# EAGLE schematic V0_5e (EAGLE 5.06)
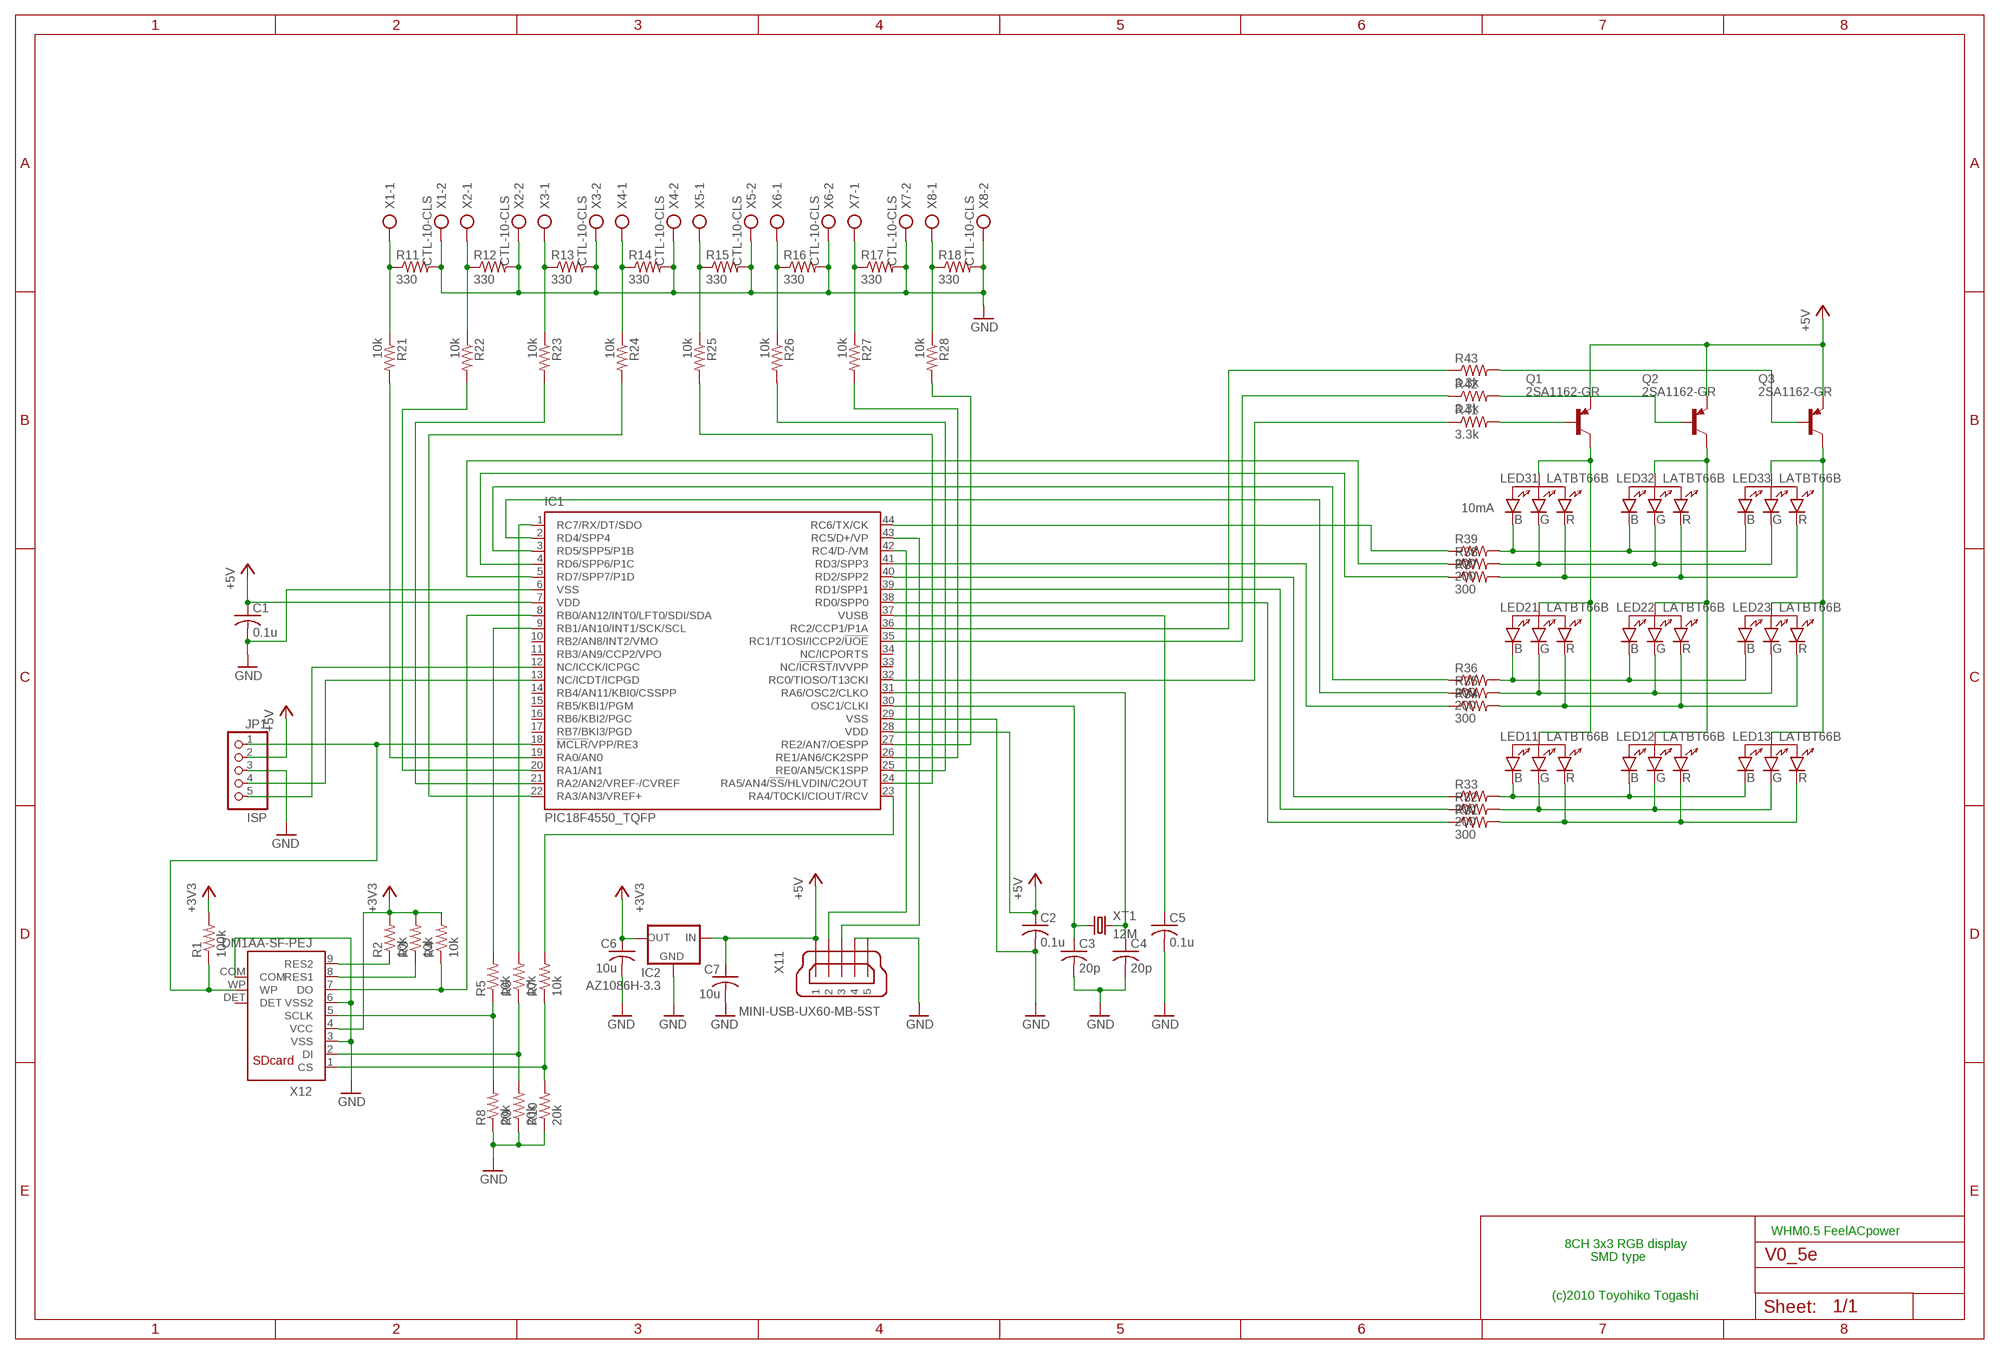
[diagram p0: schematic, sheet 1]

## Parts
C1  0.1u  C-USC0805  [C0805]
C2  0.1u  C-USC0805  [C0805]
C3  20p  C-USC0805  [C0805]
C4  20p  C-USC0805  [C0805]
C5  0.1u  C-USC0805  [C0805]
C6  10u  C-USC1206  [C1206]
C7  10u  C-USC1206  [C1206]
IC1  PIC18F4550_TQFP  [TQFP44]
IC2  AZ1086H-3.3  XC63FPP  [SOT89R]
JP1  ISP  PINHD-1X5  [1X05]
LED11  LATBT66B  [P-LCC-4]
LED12  LATBT66B  [P-LCC-4]
LED13  LATBT66B  [P-LCC-4]
LED21  LATBT66B  [P-LCC-4]
LED22  LATBT66B  [P-LCC-4]
LED23  LATBT66B  [P-LCC-4]
LED31  LATBT66B  [P-LCC-4]
LED32  LATBT66B  [P-LCC-4]
LED33  LATBT66B  [P-LCC-4]
Q1  2SA1162-GR  MMBT540LT1SMD  [SOT23-BEC]
Q2  2SA1162-GR  MMBT540LT1SMD  [SOT23-BEC]
Q3  2SA1162-GR  MMBT540LT1SMD  [SOT23-BEC]
R1  100k  R-US_M0805  [M0805]
R2  10k  R-US_M0805  [M0805]
R3  10k  R-US_M0805  [M0805]
R4  10k  R-US_M0805  [M0805]
R5  10k  R-US_M0805  [M0805]
R6  10k  R-US_M0805  [M0805]
R7  10k  R-US_M0805  [M0805]
R8  20k  R-US_M0805  [M0805]
R9  20k  R-US_M0805  [M0805]
R10  20k  R-US_M0805  [M0805]
R11  330  R-US_M0805  [M0805]
R12  330  R-US_M0805  [M0805]
R13  330  R-US_M0805  [M0805]
R14  330  R-US_M0805  [M0805]
R15  330  R-US_M0805  [M0805]
R16  330  R-US_M0805  [M0805]
R17  330  R-US_M0805  [M0805]
R18  330  R-US_M0805  [M0805]
R21  10k  R-US_M0805  [M0805]
R22  10k  R-US_M0805  [M0805]
R23  10k  R-US_M0805  [M0805]
R24  10k  R-US_M0805  [M0805]
R25  10k  R-US_M0805  [M0805]
R26  10k  R-US_M0805  [M0805]
R27  10k  R-US_M0805  [M0805]
R28  10k  R-US_M0805  [M0805]
R31  300  R-US_M0805  [M0805]
R32  200  R-US_M0805  [M0805]
R33  200  R-US_M0805  [M0805]
R34  300  R-US_M0805  [M0805]
R35  200  R-US_M0805  [M0805]
R36  200  R-US_M0805  [M0805]
R37  300  R-US_M0805  [M0805]
R38  200  R-US_M0805  [M0805]
R39  200  R-US_M0805  [M0805]
R41  3.3k  R-US_M0805  [M0805]
R42  3.3k  R-US_M0805  [M0805]
R43  3.3k  R-US_M0805  [M0805]
X1  CTL-10-CLS  AK500/2  [AK500/2]
X2  CTL-10-CLS  AK500/2  [AK500/2]
X3  CTL-10-CLS  AK500/2  [AK500/2]
X4  CTL-10-CLS  AK500/2  [AK500/2]
X5  CTL-10-CLS  AK500/2  [AK500/2]
X6  CTL-10-CLS  AK500/2  [AK500/2]
X7  CTL-10-CLS  AK500/2  [AK500/2]
X8  CTL-10-CLS  AK500/2  [AK500/2]
X11  MINI-USB-UX60-MB-5ST  [UX60-MB-5ST]
X12  DM1AA-SF-PEJ  [DM1AA]
XT1  12M  CRYSTALHC49UP  [HC49UP]

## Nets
+3V3: C6.1 IC2.3(OUT) R1.2 R2.2 R3.2 R4.2 X12.4(VCC)
+5V: C1.1 C2.1 C7.1 IC1.7(VDD) IC1.28(VDD) IC2.2(IN) JP1.2 Q1.E Q2.E Q3.E X11.1
GND: C1.2 C2.2 C3.2 C4.2 C5.2 C6.2 C7.2 IC1.6(VSS) IC1.29(VSS) IC2.1(GND) JP1.3 R8.1 R9.1 R10.1 R11.2 R12.2 R13.2 R14.2 R15.2 R16.2 R17.2 R18.2 X1.2 X2.2 X3.2 X4.2 X5.2 X6.2 X7.2 X8.2 X11.4 X12.3(VSS) X12.6(VSS2) X12.COM
N$1: IC1.39(RD1/SPP1) R32.1
N$2: IC1.22(RA3/AN3/VREF+) R24.2
N$3: IC1.21(RA2/AN2/VREF-/CVREF) R23.2
N$4: IC1.20(RA1/AN1) R22.2
N$5: R18.1 R28.1 X8.1
N$6: R5.1 R8.2 X12.5(SCLK)
N$8: R6.1 R9.2 X12.2(DI)
N$9: R7.1 R10.2 X12.1(CS)
N$10: IC1.18(!MCLR!/VPP/RE3) JP1.1 R1.1 X12.WP
N$11: LED11.P$3 LED12.P$3 LED13.P$3 R33.2
N$12: LED11.P$4 LED12.P$4 LED13.P$4 R32.2
N$13: LED11.P$1 LED12.P$1 LED13.P$1 R31.2
N$15: LED12.P$2 LED22.P$2 LED32.P$2 Q2.C
N$16: IC1.42(RC4/D-/VM) X11.2
N$17: IC1.43(RC5/D+/VP) X11.3
N$18: LED13.P$2 LED23.P$2 LED33.P$2 Q3.C
N$19: IC1.24(RA5/AN4/!SS!/HLVDIN/C2OUT) R25.2
N$20: IC1.9(RB1/AN10/INT1/SCK/SCL) R5.2
N$21: IC1.1(RC7/RX/DT/SDO) R6.2
N$22: IC1.23(RA4/T0CKI/CIOUT/RCV) R7.2
N$24: IC1.41(RD3/SPP3) R34.1
N$25: IC1.44(RC6/TX/CK) R39.1
N$26: IC1.35(RC1/T1OSI/ICCP2/!UOE) R42.1
N$28: IC1.40(RD2/SPP2) R33.1
N$29: IC1.25(RE0/AN5/CK1SPP) R26.2
N$30: IC1.13(NC/ICDT/ICPGD) JP1.4
N$31: IC1.12(NC/ICCK/ICPGC) JP1.5
N$32: IC1.26(RE1/AN6/CK2SPP) R27.2
N$33: Q1.B R41.2
N$34: IC1.27(RE2/AN7/OESPP) R28.2
N$35: Q2.B R42.2
N$36: R17.1 R27.1 X7.1
N$37: R16.1 R26.1 X6.1
N$38: R15.1 R25.1 X5.1
N$39: R14.1 R24.1 X4.1
N$40: R13.1 R23.1 X3.1
N$41: R12.1 R22.1 X2.1
N$42: R2.1 X12.9(RES2)
N$43: R3.1 X12.8(RES1)
N$44: R11.1 R21.1 X1.1
N$45: Q3.B R43.2
N$47: C4.1 IC1.31(RA6/OSC2/CLKO) XT1.2
N$49: C3.1 IC1.30(OSC1/CLKI) XT1.1
N$50: IC1.19(RA0/AN0) R21.2
N$51: LED31.P$3 LED32.P$3 LED33.P$3 R39.2
N$52: C5.1 IC1.37(VUSB)
N$53: LED31.P$4 LED32.P$4 LED33.P$4 R38.2
N$54: LED31.P$1 LED32.P$1 LED33.P$1 R37.2
N$55: LED11.P$2 LED21.P$2 LED31.P$2 Q1.C
N$56: LED21.P$3 LED22.P$3 LED23.P$3 R36.2
N$57: LED21.P$4 LED22.P$4 LED23.P$4 R35.2
N$58: LED21.P$1 LED22.P$1 LED23.P$1 R34.2
N$59: IC1.2(RD4/SPP4) R35.1
N$60: IC1.3(RD5/SPP5/P1B) R36.1
N$61: IC1.4(RD6/SPP6/P1C) R37.1
N$62: IC1.5(RD7/SPP7/P1D) R38.1
N$63: IC1.8(RB0/AN12/INT0/LFT0/SDI/SDA) R4.1 X12.7(DO)
N$64: IC1.32(RC0/TIOSO/T13CKI) R41.1
N$65: IC1.36(RC2/CCP1/P1A) R43.1
N$67: IC1.38(RD0/SPP0) R31.1
Unconnected: IC1.10(RB2/AN8/INT2/VMO) IC1.11(RB3/AN9/CCP2/VPO) IC1.14(RB4/AN11/KBI0/CSSPP) IC1.15(RB5/KBI1/PGM) IC1.16(RB6/KBI2/PGC) IC1.17(RB7/BKI3/PGD) IC1.33(NC/!ICRST!/IVVPP) IC1.34(NC/ICPORTS) X11.5 X12.DET

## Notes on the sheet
- 10mA
- WHM0.5 FeelACpower
- 8CH 3x3 RGB display
- SMD type
- (c)2010 Toyohiko Togashi

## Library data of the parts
C1-C7 = rcl:C-US: CAPACITOR, American symbol
IC1 = microchip:PIC18F4*_TQFP: USB Microcontrollers with nanoWatt Technology High-Performance, Enhanced Flash, 28/40/44-Pin, Source: http://ww1.microchip.com/downloads/en/devicedoc/39632c.pdf
IC2 = v-reg:XC63FP: Positiv Voltage Regulators www.torex.co.jp/english/product/pro02/pdf/0201_xc62fp.pdf
JP1 = pinhead:PINHD-1X5: PIN HEADER
LED11-LED13 LED21-LED23 LED31-LED33 = TOG:LATBT66B: RGB LED SMD
Q1-Q3 = transistor-pnp:MMBT540*: PNP Transistror
R1-R18 R21-R28 R31-R39 R41-R43 = rcl:R-US_: RESISTOR, American symbol
X1-X8 = con-ptr500:AK500/2: CONNECTOR
X11 = con-hirose:MINI-USB-: MINI USB Connector Source: http://www.hirose.co.jp/cataloge_hp/e24000019.pdf
X12 = TOG:DM1AA-SF-PEJ: SDcard connector HIROSE
XT1 = crystal:CRYSTAL: CRYSTAL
